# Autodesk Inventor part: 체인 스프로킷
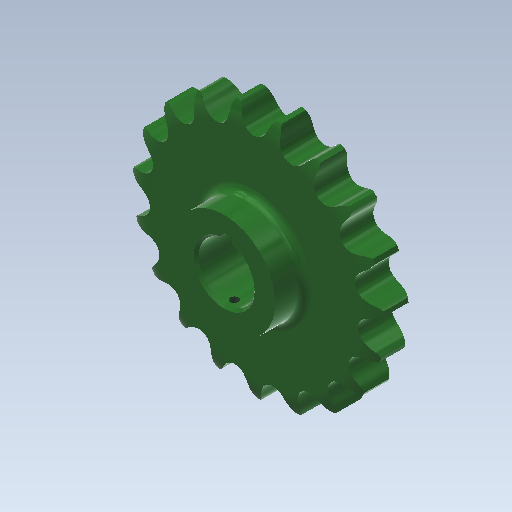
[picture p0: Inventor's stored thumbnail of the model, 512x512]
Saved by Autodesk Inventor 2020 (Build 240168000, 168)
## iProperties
CustomPartVersion: 1
Created: 2013-01
Part Number: 체인 스프로킷
Material: 강철, 연강
Document SubType Name: Modeling
Designer: mdu
Density: 1 g/cm^3
Appearance: 매끄러움 - 짙은 산림 녹색
Author: mdu
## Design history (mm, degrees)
sketch "이론적 톱니 프로파일"
  geometry: L1 (0, 0)-(0, 45.567); L2 (0, 0)-(14.795, 43.098); L3 (0, 45.567)-(14.795, 43.098); L4 (0, 45.567)-(5.661, 50.015); L5 (5.661, 50.015)-(-5.141, 45.406); L6 (-12.428, 43.493)-(-5.573, 46.417); L7 (-5.141, 45.406)-(-5.573, 46.417); L8 (5.573, 46.417)-(5.141, 45.406); L9 (0, 0)-(8.138, 48.771); A1 r 45.567 centre (0, 0) between (0, 45.567) and (14.795, 43.098); A2 r 49.445 centre (0, 0) between (7.302, 48.903) and (-7.302, 48.903); A3 r 4.545 centre (0, 45.567) between (-3.574, 42.758) and (3.574, 42.758); A4 r 7.453 centre (12.428, 43.493) between (7.302, 48.903) and (5.573, 46.417); A5 r 7.453 centre (-12.428, 43.493) between (-5.573, 46.417) and (-7.302, 48.903); A6 r 11.745 centre (5.661, 50.015) between (-5.141, 45.406) and (-3.574, 42.758); A7 r 11.745 centre (-5.661, 50.015) between (3.574, 42.758) and (5.141, 45.406); 2 further points
  constraints: 18 end point, 15 point on circle, 7 centre point, 3 coincident, 3 point on line, 3 symmetric about line, 3 tangent, 1 equal radius, 1 midpoint, 1 parallel, 1 vertical, 1 other
  dimensions: "d0" = 91.13301 diameter of A1 (computed from da_p, da_z); "d2" = 18.9474 deg angle of L2 L1 (computed from da_z); "d3" = 4.545 radius of A3 (= 0.5 x da_Dr + da_SC); "d10" = 128.158 deg angle of L4 L1 (computed from da_z); "d11" = 15.0526 deg angle of L5 L4 (computed from da_z); "d12" = 7.2 distance of L3.start L4.end (= 0.8 x da_Dr); "d13" = 11.745 distance of L4.end L5.end (= 1.3 x da_Dr + da_SC); "d14" = 12.6 distance of A4.centre L1.end (= 1.4 x da_Dr); "d23" = 4.5 distance from line of L9.end L3 (= da_Ha)
sketch "톱니 프로파일"
  geometry: L1 (0, 0)-(0, 45.567); L2 (0, 45.567)-(4.203, 43.837); L3 (0, 45.567)-(-4.203, 43.837); A1 r 4.545 centre (0, 45.567) between (-4.203, 43.837) and (4.203, 43.837); A2 r 22.68 centre (25.176, 35.206) between (7.12, 48.93) and (4.203, 43.837); A3 r 22.68 centre (-25.176, 35.206) between (-4.203, 43.837) and (-7.12, 48.93); A4 r 49.445 centre (0, 0) between (-7.12, 48.93) and (7.12, 48.93) reference; 1 further point
  constraints: 9 point on circle, 6 end point, 3 centre point, 2 tangent, 1 coincident, 1 equal radius, 1 vertical, 1 other
  dimensions: "d44" = 135.263 deg angle of L3 L2 (= da_Alfa); "d45" = 22.68 radius of A2 (= da_Re); "d46" = 4.545 radius of A1 (= da_Ri)
sketch "단면 프로파일"
  geometry: L1 (49.445, 0)-(-49.445, 0) reference; L2 (33.265, 6.65)-(-33.265, 6.65); L3 (-33.265, 6.65)-(-33.265, -6.65); L4 (-33.265, -6.65)-(33.265, -6.65); L5 (33.265, -6.65)-(33.265, 6.65); L6 (33.265, 6.65)-(49.445, 6.65); L7 (49.445, 6.65)-(49.445, -6.65); L8 (49.445, -6.65)-(33.265, -6.65); L9 (33.265, -6.65)-(33.265, 6.65); L10 (42.183, 6.65)-(0, 6.65); L11 (0, 6.65)-(0, -6.65); L12 (0, -6.65)-(42.183, -6.65); L13 (0, 6.65)-(0, -6.65); L14 (49.445, 4.775)-(49.445, -4.775); A1 r 15 centre (42.183, -8.35) between (49.445, 4.775) and (42.183, 6.65); A2 r 15 centre (42.183, 8.35) between (42.183, -6.65) and (49.445, -4.775); 2 further points
  constraints: 26 end point, 7 midpoint, 5 perpendicular, 4 parallel, 4 point on circle, 3 point on line, 3 symmetric about line, 2 centre point, 2 horizontal, 2 tangent, 1 collinear, 1 other
  dimensions: "d30" = 13.3 distance between parallel lines of L8 L6 (= da_Bf); "d31" = 66.53007 distance between parallel lines of L3 L5 (= da_Ds); "d32" = 13.3 distance between parallel lines of L4 L2 (= da_Bs); "d33" = 1.875 distance from line of L14.start L6 (= da_Ba); "d34" = 15 radius of A1 (= da_Rx); "d43" = 6.65 distance between parallel lines of L4 L1 (computed from da_k, da_pt, da_Bs)
revolve "슈라우드" stored, may be unused: angle "d36" = 90 deg
revolve "스트랜드" stored, may be unused: angle "d37" = 90 deg
extrude "이론적 톱니" cut sketch "이론적 톱니 프로파일" extent not by distance; stored distance "d18" = 10; taper "d19" = 0 deg; dims "d49" = 0, "form_type" = 0 [user parameter]
extrude "톱니" cut sketch "톱니 프로파일" extent not by distance; stored distance "d47" = 10; taper "d48" = 0 deg; dims "d50" = 10, "form_type" = 0 [user parameter]
node "타이밍 평면"
node "작업 평면3"
sketch "스케치5"
  geometry: C1 r 20 at (0, -45.567); 1 further point
  constraints: 1 centre point, 1 coincident
  dimensions: "d52" = 40 diameter of C1
extrude "돌출4" join sketch "스케치5" stored distance "d53" = 10; taper "d54" = 0 deg
sketch "스케치6"
  geometry: L1 (3, 10.583)-(3, 13.8); L2 (3, 13.8)-(-3, 13.8); L3 (-3, 13.8)-(-3, 10.583); A1 r 11 centre (0, 0) between (3, 10.583) and (-3, 10.583); 1 further point
  constraints: 6 end point, 2 parallel, 2 point on circle, 1 centre point, 1 coincident, 1 perpendicular, 1 vertical
  dimensions: "d55" = 22 diameter of A1; "d56" = 24.8 dimension on A1 L2 (computed from d55); "d57" = 6 distance of L1.end L2.end
extrude "돌출5" cut sketch "스케치6" extent not by distance; stored distance "d58" = 10; taper "d59" = 0 deg
fillet "모깎기2" dims "d60" = 3
chamfer "모따기1" distance "d61" = 1; stored, may be unused: second distance "d62" = 2, angle "d63" = 45 deg
node "작업 평면4"
sketch "스케치7"
  geometry: L1 (20, 11.7)-(-20, 11.7) reference; 2 further points
  constraints: 1 vertical alignment
  dimensions: "d64" = 4 distance from line of L1 point (0, 7.7)
hole "구멍1" sketch "스케치7" at (0, 7.7) diameter "d65" = 3.242; stored, may be unused: countersink angle "d69" = 90 deg, drill point angle "d71" = 118 deg; dims "d66" = 6, "d67" = 4, "d68" = 2, "d70" = 8
body "Solid1"
pattern_linear "스트랜드 패턴" dims "d40" = 24 (= da_pt)
pattern_circular "톱니 패턴" dims angle "d21" = 360 deg
other parameters: "da_p" = 15 [user parameter; used in 1 equation term], "da_Dr" = 9 [user parameter; used in 4 equation terms], "da_SC" = 0.045 [user parameter; used in 2 equation terms], "da_Ha" = 4.5 [user parameter; used in 1 equation term], "da_pt" = 24 [user parameter; used in 2 equation terms], "da_Bf" = 13.3 [user parameter; used in 1 equation term], "d28" = 0, "d29" = 0, "da_Ba" = 1.875 [user parameter; used in 1 equation term], "da_Rx" = 15 [user parameter; used in 1 equation term], "da_Ra" = 0.6 [user parameter], "da_Bs" = 13.3 [user parameter; used in 2 equation terms], "da_Ds" = 66.53007 [user parameter; used in 1 equation term], "d42" = 0, "da_Re" = 22.68 [user parameter; used in 1 equation term], "da_Ri" = 4.545 [user parameter; used in 1 equation term], "da_Alfa" = 135.263 deg [user parameter; used in 1 equation term], "d51" = -25
